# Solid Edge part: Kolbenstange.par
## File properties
Username: bmolnar
Dokumentum tartalom típus: 0
Author: bmolnar
Last saved by: bmolnar
Revision: 78
Sűrűség: 0,000 kg/m^3
Pontosság: 0,990
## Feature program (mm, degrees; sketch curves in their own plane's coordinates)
base feature "unnamed BaseFeature 1"
sketch for "unnamed Protrusion 1" plane through (39.2, 0, 0) normal (1, 0, 0) x-axis (0, 0, -1)
  circle centre (0, 0) radius 25
extrude "unnamed Protrusion 1" add finite 17.6 along +normal
sketch for "Kihúzás_2" #1 plane through (39.2, 0, 0) normal (1, 0, 0) x-axis (0, 0, -1)
  circle centre (0, 0) radius 8
sketch for "Kihúzás_2" #2 plane through (39.2, 0, 0) normal (1, 0, 0) x-axis (0, 0, -1)
  circle centre (0, 0) radius 25
extrude "Kihúzás_2" add finite 9.4 along -normal
sketch for "Furat_1" plane through (-2, 0, 0.0012) normal (-1, 0, 0) x-axis (0, 1, 0)
hole "Furat_1" diameter 6.65 finite  VBottomAngle = 118 deg
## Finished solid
Body 1: solid body, 14 faces, 20 edges, 8 vertices.
  Faces by surface: plane 8, cylinder 4, cone 1, torus 1
  Edges by curve: circle 10, line 6, curve on surface 2, ellipse 2
Bounding box of the edges (mm; curved faces can reach further): 61.800 x 50.000 x 50.000, from (-5, -25, -25) to (56.8, 25, 25).
Cylindrical faces by radius (mm): R3.325 x1, R4.125 x1, R8 x1, R25 x1
Conical faces (half-angle, radius in mm at the cone's reference point): 59 deg R3.325 x1
Toroidal faces (ring radius, tube radius in mm): R6.2 r1.8 x1
Planar faces by outward normal: +x 1, +y 1, -x 3, -y 1, oblique 2
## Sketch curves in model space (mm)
circle centre (39.2, 0, 0) radius 25
circle centre (39.2, 0, 0) radius 8
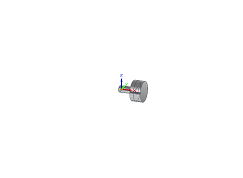
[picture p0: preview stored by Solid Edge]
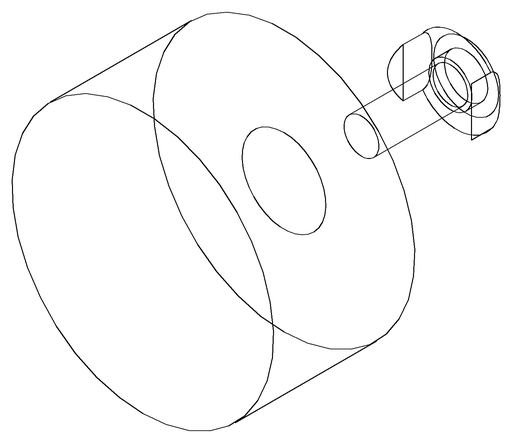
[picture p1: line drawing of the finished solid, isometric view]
